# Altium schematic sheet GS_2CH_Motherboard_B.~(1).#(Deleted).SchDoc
size 381 x 254 mm
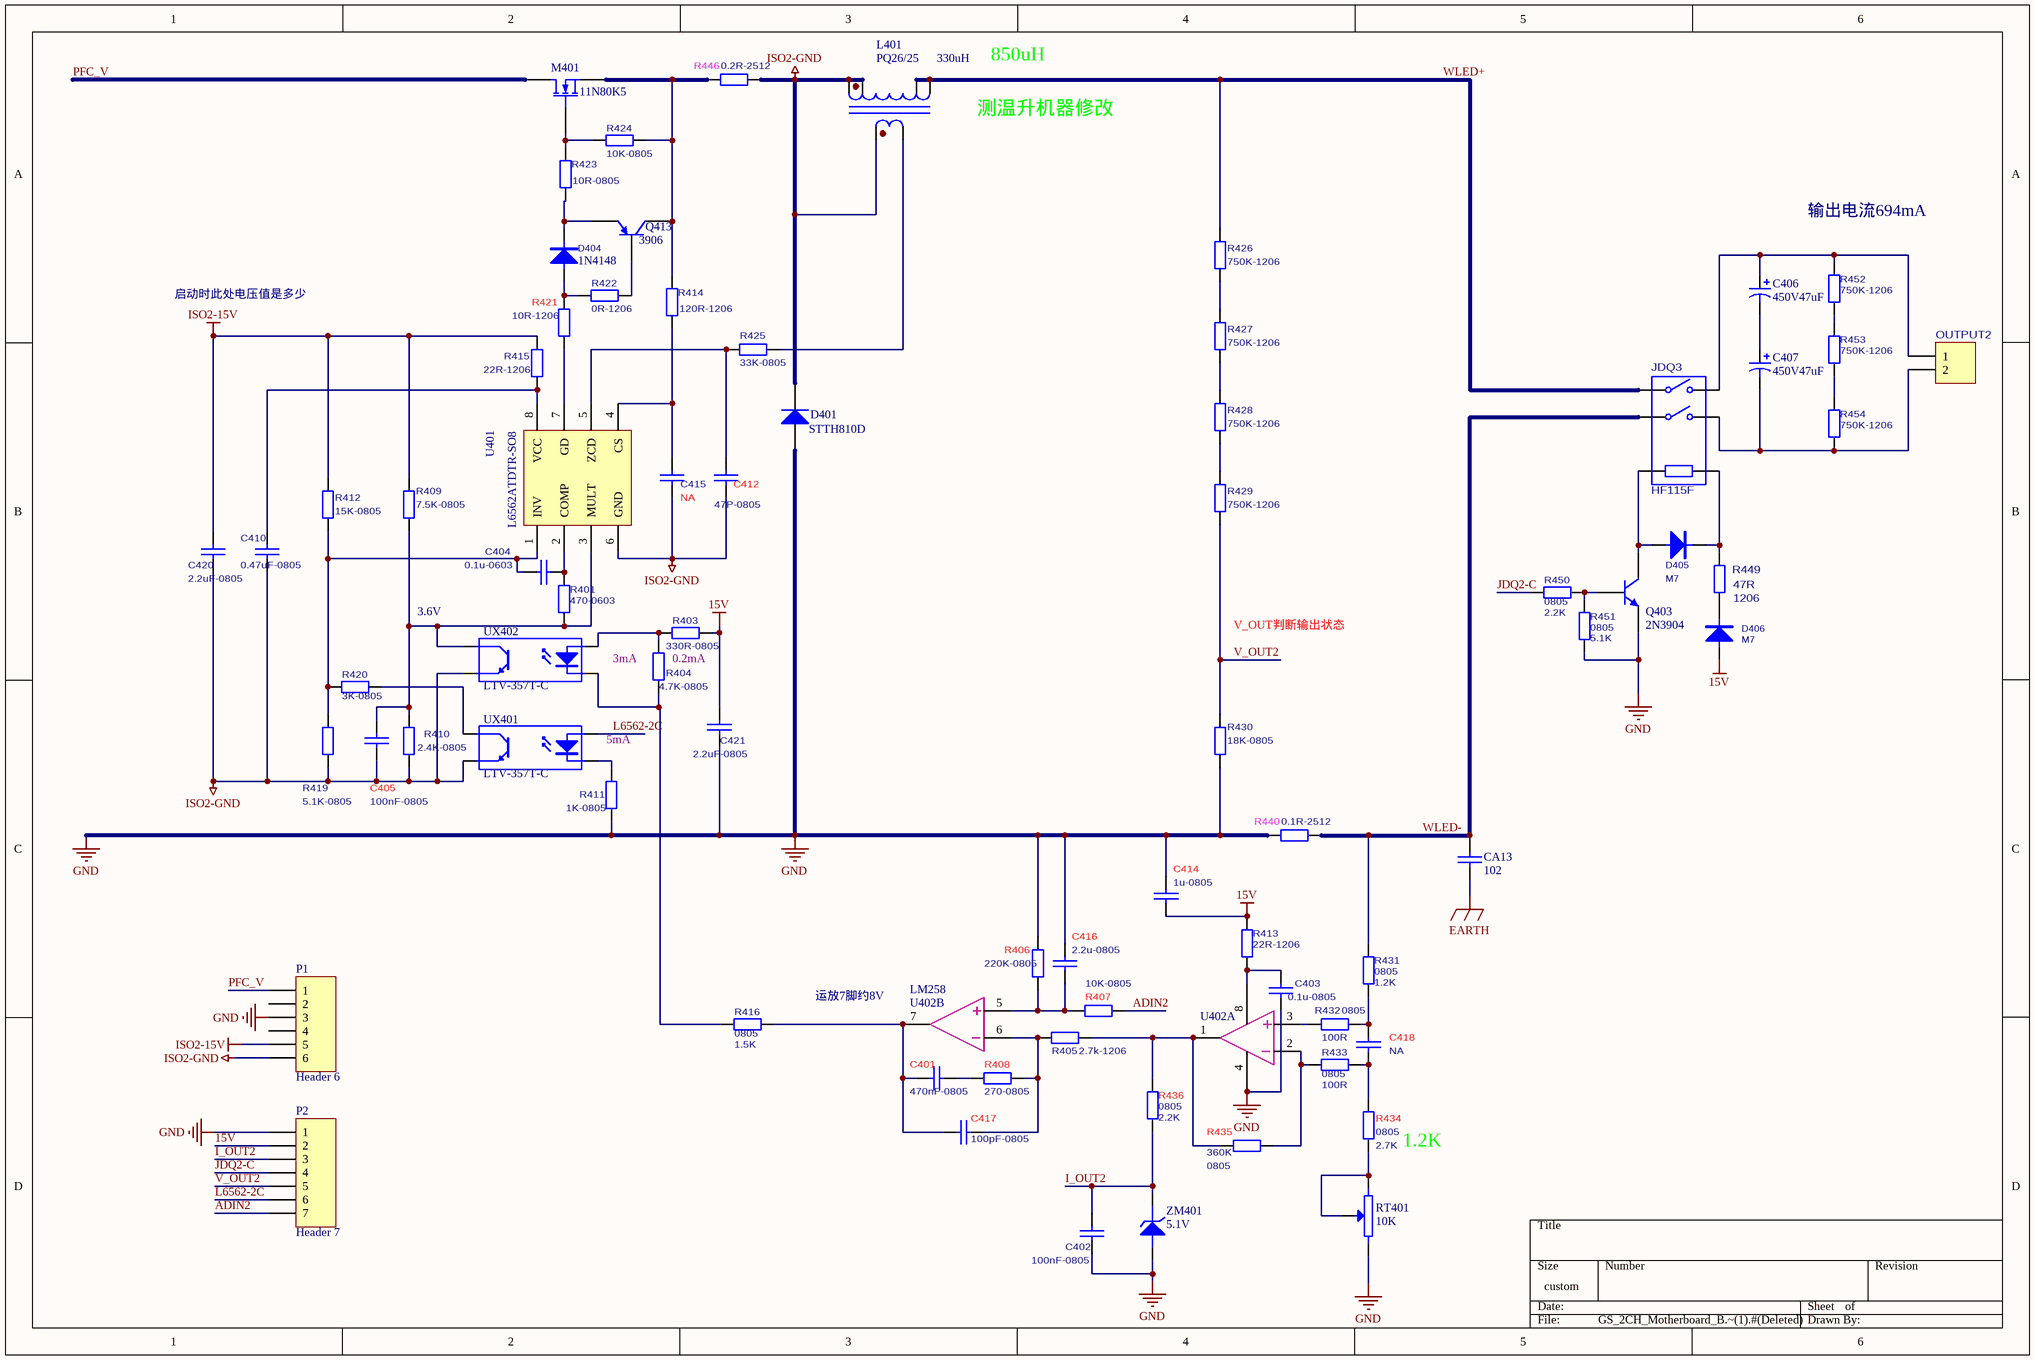
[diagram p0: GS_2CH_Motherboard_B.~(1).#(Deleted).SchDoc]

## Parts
C401  value 470nF-0805  [RW0805]
C402  value 100nF-0805  [RW0805]  (hidden comment: 0805)
C403  value 0.1u-0805  [RW0805]  (hidden comment: 301008)
C404  value 0.1u-0603  [RW0603]
C405  value 100nF-0805  [RW0805]  (hidden comment: 301008)
C406  450V47uF  [CE12.5]
C407  450V47uF  [CE12.5]
C410  value 0.47uF-0805  [RW0805]  (hidden comment: 301009)
C412  301001  [RW0805]  (value not drawn)
C414  value 1u-0805  [RW0805]  (hidden comment: 301008)
C415  (no value)  [RW0805]
C416  value 2.2u-0805  [RW0805]  (hidden comment: 301008)
C417  value 100pF-0805  [RW0805]  (hidden comment: 301008)
C418  value NA  [RW0805]  (hidden comment: 0805)
C420  value 2.2uF-0805  [RW0805]  (hidden comment: 301013)
C421  value 2.2uF-0805  [RW0805]  (hidden comment: 301013)
CA13  102  [Y2C]
D401  value STTH810D  [TO-220-KA]  (hidden comment: 308006)
D404  value 1N4148  [SOD-123]  (hidden comment: 307004)
D405  M7  [SMA]
D406  M7  [SMA]
JDQ3  HF115F  [RELAY-HF115F]
L401  PQ26/25  value 330uH  [T-PQ2625]
M401  value 11N80K5  [TO220VS]  (hidden comment: 314012)
OUTPUT2  322055  [JST-3.96-2P]  (value not drawn)
P1  Header 6  [6P插座]
P2  Header 7  [2.0*7]
Q403  2N3904  [SOT-23-BEC]
Q413  value 3906  [SOT-23-BEC]  (hidden comment: 309005)
R401  value 470-0603  [RW0603]
R403  value 330R-0805  [RW0805]
R404  value 4.7K-0805  [RW0805]
R405  value 2.7k-1206  [RW1206]
R406  value 220K-0805  [RW0805]
R407  value 10K-0805  [RW0805]  (hidden comment: 303020)
R408  value 270-0805  [RW0805]  (hidden comment: 303046)
R409  value 7.5K-0805  [RW0805]
R410  value 2.4K-0805  [RW0805]
R411  value 1K-0805  [RW0805]
R412  value 15K-0805  [RW0805]  (hidden comment: 303053)
R413  value 22R-1206  [RW1206]  (hidden comment: 303074)
R414  value 120R-1206  [RW1206]
R415  value 22R-1206  [RW1206]  (hidden comment: 303074)
R416  0805  value 1.5K  [RW0805]
R419  value 5.1K-0805  [RW0805]
R420  value 3K-0805  [RW0805]
R421  value 10R-1206  [RW1206]  (hidden comment: 303075)
R422  value 0R-1206  [RW1206]
R423  value 10R-0805  [RW0805]  (hidden comment: 303073)
R424  value 10K-0805  [RW0805]  (hidden comment: 303043)
R425  value 33K-0805  [RW0805]  (hidden comment: 303055)
R426  value 750K-1206  [RW1206]  (hidden comment: 303094)
R427  value 750K-1206  [RW1206]  (hidden comment: 303094)
R428  value 750K-1206  [RW1206]  (hidden comment: 303094)
R429  value 750K-1206  [RW1206]  (hidden comment: 303094)
R430  value 18K-0805  [RW0805]  (hidden comment: 303033)
R431  0805  value 1.2K  [RW0805]
R432  0805  value 100R  [RW0805]
R433  0805  value 100R  [RW0805]
R434  0805  value 2.7K  [RW0805]
R435  0805  value 360K  [RW0805]
R436  0805  value 2.2K  [RW0805]
R440  value 0.1R-2512  [RW2512]
R446  value 0.2R-2512  [RW2512]
R449  1206  value 47R  [RW1206]
R450  0805  value 2.2K  [RW0805]
R451  0805  value 5.1K  [RW0805]
R452  value 750K-1206  [RW1206]  (hidden comment: 303094)
R453  value 750K-1206  [RW1206]  (hidden comment: 303094)
R454  value 750K-1206  [RW1206]  (hidden comment: 303094)
RT401  10K  [直插电位器]
U401  value L6562ATDTR-SO8  [SO-8]  (hidden comment: 311046)
U402  311026  [SOP-8]  (value not drawn)  (parts A,B of 2)
UX401  value LTV-357T-C  [LTV]  (hidden comment: 317001)
UX402  value LTV-357T-C  [LTV]  (hidden comment: 317001)
ZM401  5.1V  [二极管]

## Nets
15V: C414.1 C421.1 D406.A P2.2 R403.1 R413.2
EARTH: CA13.2
GND: C402.2 C403.2 C414.2 C416.2 C421.2 D401.1 P1.3 P2.1 Q403.E R406.1 R411.1 R430.1 R440.1 R451.1 RT401.3 U402.4(U-) ZM401.1(A)
ISO2-15V: C420.1 P1.5 R409.2 R412.1 R415.2
ISO2-GND: C405.1 C410.2 C412.2 C415.2 C420.2 D401.3 L401.5 L401.8 L401.9 P1.6 R410.1 R419.1 R446.2 U401.6(GND) UX401.3(E) UX402.3(E)
ADIN2: P2.7 R407.2
I_OUT2: C402.1 P2.3 R436.2 ZM401.2(K)
JDQ2-C: P2.4 R450.1
L6562-2C: P2.6 UX401.1(A)
PFC_V: M401.2 P1.1
V_OUT2: P2.5 R429.2 R430.2
WLED+: JDQ3.6 L401.10 L401.11 R426.1
WLED-: CA13.1 JDQ3.5 R431.1 R440.2
NetC401_1: C401.1 R408.1
NetC401_2: C401.2 C417.2 R416.2 U402.7
NetC403_1: C403.1 R413.1 U402.8(U+)
NetC404_1: C404.1 R401.1 U401.2(COMP)
NetC404_2: C404.2 R412.2 R419.2 R420.2 U401.1(INV)
NetC405_2: C405.2 R401.2 R409.1 R410.2 U401.3(MULT) UX402.4(C)
NetC406_+: C406.+ JDQ3.4 OUTPUT2.1 R452.2
NetC406_-: C406.- C407.+
NetC407_-: C407.- JDQ3.3 OUTPUT2.2 R454.1
NetC410_1: C410.1 R415.1 U401.8(VCC)
NetC412_1: C412.1 R425.1 U401.5(ZCD)
NetC415_1: C415.1 R414.1 U401.4(CS)
NetC416_1: C416.1 R406.2 R407.1 U402.5
NetC417_1: C417.1 R405.1 R408.2 U402.6
NetC418_1: C418.1 R431.2 R432.1
NetC418_2: C418.2 R433.2 R434.1
NetD404_A: D404.A R421.1 R422.1
NetD404_K: D404.K Q413.E R423.1
NetD405_A: D405.A JDQ3.1 Q403.C
NetD405_K: D405.K JDQ3.2 R449.2
NetD406_K: D406.K R449.1
NetL401_2: L401.2 R425.2
NetM401_1: M401.1 R423.2 R424.2
NetM401_3: M401.3 Q413.C R414.2 R424.1 R446.1
NetQ403_B: Q403.B R450.2 R451.2
NetQ413_B: Q413.B R422.2
NetR403_2: R403.2 R404.1 UX402.1(A)
NetR404_2: R404.2 R416.1 UX402.2(K)
NetR405_2: R405.2 R435.2 R436.1 U402.1
NetR411_2: R411.2 UX401.2(K)
NetR420_1: R420.1 UX401.4(C)
NetR421_2: R421.2 U401.7(GD)
NetR426_2: R426.2 R427.1
NetR427_2: R427.2 R428.1
NetR428_2: R428.2 R429.1
NetR432_2: R432.2 U402.3
NetR433_1: R433.1 R435.1 U402.2
NetR434_2: R434.2 RT401.1 RT401.2
NetR452_1: R452.1 R453.2
NetR453_1: R453.1 R454.2

Not connected (* = marked no-connect by the designer): P1 2 4

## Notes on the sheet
- 850uH
- (near L401) 测温升机器修改
- 输出电流694mA
- 启动时此处电压值是多少
- (near UX402) 3.6V
- V_OUT判断输出状态
- 3mA
- 0.2mA
- 5mA
- 运放7脚约8V
- 1.2K

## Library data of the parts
C401 C403-C405 C414 C416 C417 = CAP: 贴片电容
C402 C418 = C
C406 C407 = Cap Pol2: Polarized Capacitor (Axial); Value: 2.2uF 275VAC
C410 C412 C415 C420 C421 = C: 贴片电容
CA13 = CAP: Capacitor
D401 = Diode 1N914: 直插二极管; pin to pad: 1>A 3>K
D404 = DIO: 贴片二极管
D405 D406 = DIO
JDQ3 = Relay - 两组常开: Dual-Pole Single-Throw Relay
L401 = inductance2
M401 = MOSFET-N: TO220mos管; PackageDocument: 1995/1996
OUTPUT2 = Header 2: 接线端子
P1 = Header 6: Header, 6-Pin
P2 = Header 7: Header, 7-Pin
Q403 = NPN: NPN Bipolar Transistor
Q413 = PNP: 贴片三极管
R401 R403-R415 R419-R430 R440 R446 R452-R454 = Res2: 贴片电阻
R416 R431-R436 R449-R451 = Res2: Resistor
RT401 = POT2
U401 = L6562: 贴片集成电路
U402 = LM393: 贴片集成电路
UX401 UX402 = Optoisolator1: 贴片光耦
ZM401 = 稳压管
